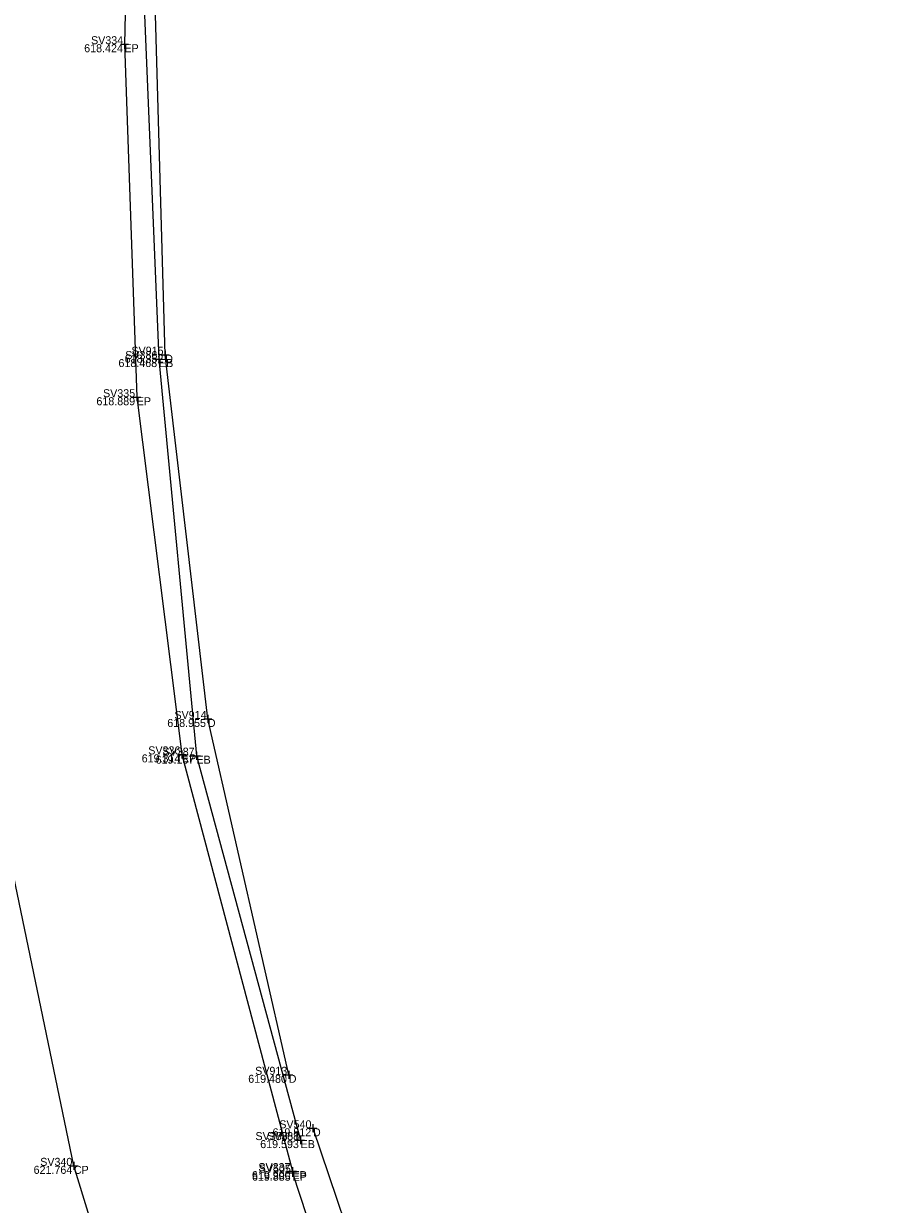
# Model space of a CAD drawing. Extents: x -2 to 1979875, y -2 to 232027.
# Drawn here: x 1978753 to 1978807.1, y 230727.4 to 230801.2 of the extents above; entities that cross this region are included whole.
import ezdxf

# ---------------------------------------------------------------- set-up
doc = ezdxf.new("R2010")
doc.units = 0
for name, color, linetype in [('_CIVIL_CONSTRUCTION', 7, 'Continuous'), ('DR_X_Ditch', 7, 'Continuous'), ('GE_X_Alignment', 7, 'Continuous'), ('GE_X_Alignment_1000_Curve_Data', 7, 'Continuous'), ('GE_X_Alignment_1000_Stations', 7, 'Continuous'), ('GE_X_Alignment_100_Curve_Data', 7, 'Continuous'), ('GE_X_Alignment_100_Stations', 7, 'Continuous'), ('SC_Scratch1', 7, 'Continuous')]:
    doc.layers.add(name, color=color, linetype=linetype)

msp = doc.modelspace()

# ---------------------------------------------------------------- linework, layer by layer
at = {"layer": 'DR_X_Ditch'}
for points in [[(1978769.61, 230735.533), (1978764.556, 230757.762), (1978761.888, 230780.52), (1978761.255, 230802.491), (1978762.758, 230825.129), (1978765.137, 230850.029), (1978768.569, 230875.252), (1978770.473, 230901.75), (1978772.394, 230926.88), (1978774.225, 230946.118), (1978776.188, 230970.1), (1978776.947, 230991.277), (1978778.808, 231013.722), (1978780.679, 231036.008), (1978780.852, 231047.689), (1978785.42, 231078.945), (1978790.697, 231097.051), (1978792.307, 231119.545), (1978794.395, 231141.248), (1978795.023, 231162.503), (1978796.552, 231185.182), (1978801.304, 231199.708)], [(1978771.125, 230732.191), (1978778.159, 230711.366), (1978786.031, 230691.476), (1978794.555, 230673.399), (1978804.965, 230654.98), (1978815.554, 230639.968), (1978828.294, 230624.497), (1978844.456, 230606.581), (1978859.572, 230591.097), (1978875.392, 230576.708), (1978886.516, 230567.847)]]:
    msp.add_lwpolyline(points, dxfattribs=at)
at = {"layer": 'GE_X_Alignment_1000_Curve_Data'}
msp.add_lwpolyline([(1978771.368, 230686.901), (1978762.945, 230707.808), (1978756.184, 230729.845), (1978751.49, 230752.309), (1978748.994, 230772.916), (1978748.08, 230796.049), (1978747.937, 230796.247), (1978748.471, 230819.071), (1978749.254, 230839.296), (1978750.532, 230861.092), (1978751.977, 230883.907), (1978753.538, 230907.259), (1978755.272, 230931.005), (1978756.708, 230952.708), (1978758.182, 230974.871), (1978759.598, 230998.872), (1978761.121, 231023.464)], dxfattribs=at)
at = {"layer": 'GE_X_Alignment_1000_Stations'}
for points in [[(1978785.568, 231251.827), (1978784.19, 231242.096), (1978782.784, 231222.648), (1978782.32, 231202.663), (1978780.702, 231177.057), (1978778.946, 231150.803), (1978777.805, 231126.797), (1978776.986, 231106.931), (1978775.705, 231085.257), (1978774.572, 231063.753), (1978773.517, 231041.76), (1978772.029, 231016.51), (1978770.7, 230994.507), (1978769.257, 230972.092), (1978767.73, 230948.595), (1978766.192, 230924.232), (1978764.603, 230899.039), (1978762.827, 230873.547), (1978761.273, 230848.668), (1978759.848, 230822.744), (1978759.345, 230799.915), (1978760.114, 230777.862), (1978762.938, 230755.551), (1978769.839, 230729.514)], [(1978769.847, 230729.415), (1978776.553, 230708.98), (1978784.668, 230690.309), (1978794.119, 230671.233), (1978804.682, 230653.303), (1978817.78, 230635.658), (1978827.58, 230622.57), (1978841.659, 230607.55), (1978855.429, 230592.978), (1978873.114, 230576.871), (1978893.268, 230560.833), (1978915.513, 230544.403), (1978933.587, 230531.196), (1978953.659, 230517.09), (1978973.227, 230503.602), (1978990.133, 230491.392), (1979010.591, 230476.223), (1979030.079, 230461.641), (1979044.057, 230451.677)]]:
    msp.add_lwpolyline(points, dxfattribs=at)
at = {"layer": 'GE_X_Alignment_100_Curve_Data'}
for p, q in [((1978759.095, 230799.915), (1978759.595, 230799.915)), ((1978759.345, 230800.165), (1978759.345, 230799.665)), ((1978759.345, 230799.915), (1978759.345, 230799.915)), ((1978761.5, 230780.497), (1978761.5, 230779.997)), ((1978761.638, 230780.52), (1978762.138, 230780.52)), ((1978761.888, 230780.77), (1978761.888, 230780.27)), ((1978761.888, 230780.52), (1978761.888, 230780.52)), ((1978761.25, 230780.247), (1978761.75, 230780.247)), ((1978761.5, 230780.247), (1978761.5, 230780.247)), ((1978760.114, 230778.112), (1978760.114, 230777.612)), ((1978759.864, 230777.862), (1978760.364, 230777.862)), ((1978760.114, 230777.862), (1978760.114, 230777.862)), ((1978764.306, 230757.762), (1978764.806, 230757.762)), ((1978764.556, 230758.012), (1978764.556, 230757.512)), ((1978764.556, 230757.762), (1978764.556, 230757.762)), ((1978762.688, 230755.551), (1978763.188, 230755.551)), ((1978762.938, 230755.801), (1978762.938, 230755.301)), ((1978762.938, 230755.551), (1978762.938, 230755.551)), ((1978763.595, 230755.469), (1978764.095, 230755.469)), ((1978763.845, 230755.719), (1978763.845, 230755.219)), ((1978763.845, 230755.469), (1978763.845, 230755.469)), ((1978769.36, 230735.533), (1978769.86, 230735.533)), ((1978769.61, 230735.783), (1978769.61, 230735.283)), ((1978769.61, 230735.533), (1978769.61, 230735.533)), ((1978771.125, 230732.441), (1978771.125, 230731.941)), ((1978770.352, 230731.704), (1978770.352, 230731.204)), ((1978770.352, 230731.704), (1978770.352, 230731.204)), ((1978770.875, 230732.191), (1978771.375, 230732.191)), ((1978771.125, 230732.191), (1978771.125, 230732.191)), ((1978770.102, 230731.454), (1978770.602, 230731.454)), ((1978770.102, 230731.454), (1978770.602, 230731.454)), ((1978770.352, 230731.454), (1978770.352, 230731.454)), ((1978770.352, 230731.454), (1978770.352, 230731.454)), ((1978755.934, 230729.845), (1978756.434, 230729.845)), ((1978756.184, 230730.095), (1978756.184, 230729.595)), ((1978756.184, 230729.845), (1978756.184, 230729.845)), ((1978769.589, 230729.514), (1978770.089, 230729.514)), ((1978769.597, 230729.415), (1978770.097, 230729.415)), ((1978769.839, 230729.764), (1978769.839, 230729.264)), ((1978769.839, 230729.514), (1978769.839, 230729.514)), ((1978769.847, 230729.665), (1978769.847, 230729.165)), ((1978769.847, 230729.415), (1978769.847, 230729.415))]:
    msp.add_line(p, q, dxfattribs=at)
at = {"layer": 'SC_Scratch1'}
msp.add_lwpolyline([(1978787.694, 231249.601), (1978785.48, 231226.833), (1978784.558, 231206.407), (1978783.016, 231187.193), (1978782.112, 231167.584), (1978780.51, 231145.937), (1978779.287, 231125.907), (1978778.425, 231108.773), (1978777.775, 231087.524), (1978776.748, 231064.782), (1978775.35, 231040.582), (1978774.462, 231016.281), (1978772.549, 230990.683), (1978771.051, 230965.635), (1978769.086, 230942.407), (1978767.324, 230917.989), (1978765.95, 230893.701), (1978764.896, 230870.53), (1978763.088, 230848.633), (1978761.583, 230826.273), (1978760.498, 230804.271), (1978761.5, 230780.247), (1978763.845, 230755.469), (1978770.352, 230731.454)], dxfattribs=at)

# ---------------------------------------------------------------- texts
at = {"layer": '_CIVIL_CONSTRUCTION'}
for s, p in [('618.424', (1978756.829, 230799.415)), ('618.352', (1978759.36, 230780.02)), ('618.468', (1978758.97, 230779.747)), ('618.889', (1978757.593, 230777.362)), ('618.955', (1978762.021, 230757.262)), ('619.314', (1978760.422, 230755.051)), ('619.157', (1978761.294, 230754.969)), ('619.480', (1978767.08, 230735.033)), ('619.512', (1978768.597, 230731.691)), ('619.593', (1978767.827, 230730.954)), ('619.593', (1978767.827, 230730.954)), ('621.764', (1978753.668, 230729.345)), ('619.900', (1978767.309, 230729.014)), ('619.885', (1978767.312, 230728.915))]:
    msp.add_text(s, height=0.5, dxfattribs=at).set_placement(p)
at = {"layer": 'GE_X_Alignment'}
for s, p in [('SV334', (1978757.256, 230799.915)), ('SV915', (1978759.779, 230780.52)), ('SV386', (1978759.395, 230780.247)), ('SV335', (1978758.005, 230777.862)), ('SV914', (1978762.467, 230757.762)), ('SV336', (1978760.833, 230755.551)), ('SV387', (1978761.72, 230755.469)), ('SV913', (1978767.512, 230735.533)), ('SV540', (1978769.021, 230732.191)), ('SV388_1', (1978767.532, 230731.454)), ('SV388', (1978768.249, 230731.454)), ('SV340', (1978754.08, 230729.845)), ('SV337', (1978767.714, 230729.514)), ('SV505', (1978767.738, 230729.415))]:
    msp.add_text(s, height=0.5, dxfattribs=at).set_placement(p)
at = {"layer": 'GE_X_Alignment_100_Stations'}
for s, p in [('EP', (1978759.345, 230799.415)), ('D', (1978761.888, 230780.02)), ('EB', (1978761.5, 230779.747)), ('EP', (1978760.114, 230777.362)), ('D', (1978764.556, 230757.262)), ('EP', (1978762.938, 230755.051)), ('EB', (1978763.845, 230754.969)), ('D', (1978769.61, 230735.033)), ('D', (1978771.125, 230731.691)), ('EB', (1978770.352, 230730.954)), ('EL', (1978770.352, 230730.954)), ('CP', (1978756.184, 230729.345)), ('EP', (1978769.839, 230729.014)), ('EP', (1978769.847, 230728.915))]:
    msp.add_text(s, height=0.5, dxfattribs=at).set_placement(p)

doc.saveas('drawing.dxf')
